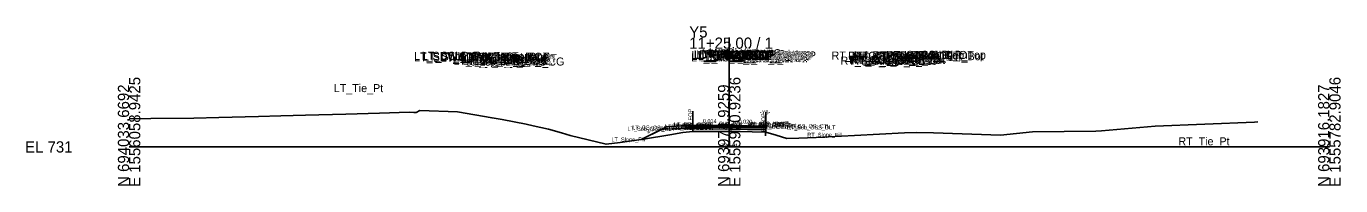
# Model space of a CAD drawing. Extents: x -26 to 4229, y -10 to 9523.
# Drawn here: x -25.7 to 302.8, y 1990.3 to 2030.1 of the extents above; entities that cross this region are included whole.
import ezdxf

# ---------------------------------------------------------------- set-up
doc = ezdxf.new("R2010")
doc.units = 0
for name, color, linetype in [('Default', 7, 'Continuous'), ('Exist Cross Section Cell', 7, 'Continuous'), ('Exist XS Center Line Elevation Label', 7, 'Continuous'), ('Exist XS Ground Line', 7, 'Continuous'), ('Old_Level_63', 7, 'Continuous'), ('Prop CMT Pvmt Course 1', 7, 'Continuous'), ('Prop CMT Pvmt Course 2', 7, 'Continuous'), ('Prop CMT Pvmt Course 3', 7, 'Continuous'), ('Prop CMT Pvmt Surface', 7, 'Continuous'), ('Prop CMT Pvmt Surface Shoulder', 7, 'Continuous'), ('Prop CMT Shld Paved Course 1', 7, 'Continuous'), ('Prop CMT Shld Paved Course 2', 7, 'Continuous'), ('Prop CMT Shld Paved Course 3', 7, 'Continuous'), ('Prop CMT Slope Grass', 7, 'Continuous'), ('Prop CMT Subgrade Earthwork', 7, 'Continuous'), ('Prop XS Earthwork Shape', 7, 'Continuous'), ('Prop XS Label Text', 7, 'Continuous'), ('Prop XSC Text', 7, 'Continuous'), ('Scratch_Level_1', 7, 'Continuous')]:
    doc.layers.add(name, color=color, linetype=linetype)

msp = doc.modelspace()

# ---------------------------------------------------------------- linework, layer by layer
at = {"layer": 'Exist Cross Section Cell'}
for p, q in [((150, 2000), (150, 2027.33)), ((0, 2000), (150, 2000)), ((150, 2000), (300, 2000))]:
    msp.add_line(p, q, dxfattribs=at)
at = {"layer": 'Exist XS Ground Line'}
msp.add_lwpolyline([(0, 2007.03), (5.43, 2007.07), (16.15, 2007.19), (22.43, 2007.34), (32.35, 2007.62), (37.96, 2007.79), (44.11, 2007.93), (54.16, 2008.19), (62.55, 2008.45), (70.03, 2008.64), (71.21, 2008.63), (71.78, 2008.63), (72.64, 2009.11), (82.09, 2008.73), (90.75, 2007.23), (93.26, 2006.81), (99.28, 2005.66), (101.04, 2005.27), (104.81, 2004.46), (108.09, 2003.48), (110.25, 2002.89), (119.22, 2000.68), (122.77, 2001.09), (128.6, 2001.91), (135.17, 2003.03), (138.44, 2003.62), (140.89, 2003.89), (147.47, 2003.83), (150, 2003.81), (150.37, 2003.81), (152.44, 2003.81), (159.14, 2003.65), (161.72, 2002.94), (164.41, 2002.07), (167.4, 2002.18), (173.89, 2002.43), (174.83, 2002.5), (181.29, 2002.88), (193.78, 2003.51), (196.75, 2003.64), (201.06, 2003.55), (217.77, 2002.96), (225.79, 2003.79), (241.6, 2003.97), (243.01, 2004), (256.47, 2005.22), (281.27, 2006.21), (282.14, 2006.25)], dxfattribs=at)
at = {"layer": 'Old_Level_63'}
msp.add_line((159.06, 2008.02), (159.06, 2002.73), dxfattribs=at)
at = {"layer": 'Prop CMT Pvmt Course 1'}
for points in [[(150, 2005.34), (140.3, 2005.47)], [(140.3, 2005.47), (140.3, 2005.22)], [(140.3, 2005.22), (150, 2005.09)], [(150, 2005.09), (150, 2005.34)], [(150, 2005.34), (159.06, 2005.15)], [(150, 2005.09), (150, 2005.34)], [(159.06, 2004.9), (150, 2005.09)], [(159.06, 2005.15), (159.06, 2004.9)]]:
    msp.add_lwpolyline(points, dxfattribs=at)
at = {"layer": 'Prop CMT Pvmt Course 2'}
for points in [[(150, 2005.09), (140.3, 2005.22)], [(140.3, 2005.22), (140.3, 2004.97)], [(140.3, 2004.97), (150, 2004.84)], [(150, 2004.84), (150, 2005.09)], [(150, 2004.84), (150, 2005.09)], [(150, 2005.09), (159.06, 2004.9)], [(159.06, 2004.65), (150, 2004.84)], [(159.06, 2004.9), (159.06, 2004.65)]]:
    msp.add_lwpolyline(points, dxfattribs=at)
at = {"layer": 'Prop CMT Pvmt Course 3'}
for points in [[(150, 2004.84), (140.3, 2004.97)], [(140.3, 2004.97), (140.3, 2004.6)], [(140.3, 2004.6), (150, 2004.46)], [(150, 2004.46), (150, 2004.84)], [(150, 2004.84), (159.06, 2004.65)], [(150, 2004.46), (150, 2004.84)], [(159.06, 2004.28), (150, 2004.46)], [(159.06, 2004.65), (159.06, 2004.28)]]:
    msp.add_lwpolyline(points, dxfattribs=at)
at = {"layer": 'Prop CMT Pvmt Surface'}
for points in [[(150, 2005.34), (140.3, 2005.47)], [(150, 2005.34), (159.06, 2005.15)]]:
    msp.add_lwpolyline(points, dxfattribs=at)
at = {"layer": 'Prop CMT Pvmt Surface Shoulder'}
for points in [[(140.3, 2005.47), (140.3, 2005.47)], [(159.06, 2005.15), (159.06, 2005.15)]]:
    msp.add_lwpolyline(points, dxfattribs=at)
at = {"layer": 'Prop CMT Shld Paved Course 1'}
for points in [[(140.3, 2005.47), (140.05, 2005.22)], [(140.05, 2005.22), (140.3, 2005.22)], [(140.3, 2005.47), (140.3, 2005.47)], [(140.3, 2005.22), (140.3, 2005.47)], [(159.06, 2005.15), (159.06, 2005.15)], [(159.06, 2004.9), (159.06, 2005.15)]]:
    msp.add_lwpolyline(points, dxfattribs=at)
at = {"layer": 'Prop CMT Shld Paved Course 2'}
for points in [[(140.3, 2005.22), (140.05, 2005.22), (139.79, 2004.96)], [(139.79, 2004.96), (140.3, 2004.97)], [(140.3, 2004.97), (140.3, 2005.22)], [(159.06, 2004.65), (159.06, 2004.9)]]:
    msp.add_lwpolyline(points, dxfattribs=at)
at = {"layer": 'Prop CMT Shld Paved Course 3'}
for points in [[(140.3, 2004.97), (139.79, 2004.96), (139.29, 2004.95), (138.91, 2004.57)], [(138.91, 2004.57), (140.3, 2004.6)], [(140.3, 2004.6), (140.3, 2004.97)], [(159.06, 2004.28), (159.06, 2004.65)]]:
    msp.add_lwpolyline(points, dxfattribs=at)
at = {"layer": 'Prop CMT Slope Grass'}
msp.add_lwpolyline([(140.3, 2005.47), (134.3, 2004.99), (127.97, 2001.82)], dxfattribs=at)
at = {"layer": 'Prop CMT Subgrade Earthwork'}
msp.add_line((159.06, 2005.15), (159.06, 2003.65), dxfattribs=at)
for points in [[(138.91, 2004.57), (133.23, 2004.46)], [(140.3, 2004.6), (138.91, 2004.57)], [(150, 2004.46), (140.3, 2004.6)], [(150, 2004.46), (159.06, 2004.28)], [(159.06, 2004.28), (159.06, 2003.65)]]:
    msp.add_lwpolyline(points, dxfattribs=at)
at = {"layer": 'Prop XS Earthwork Shape'}
msp.add_lwpolyline([(159.06, 2004.28), (159.06, 2003.65), (152.44, 2003.81), (150.37, 2003.81), (150, 2003.81), (147.47, 2003.83), (140.89, 2003.89), (138.44, 2003.62), (135.17, 2003.03), (128.6, 2001.91), (127.97, 2001.82), (133.23, 2004.46), (138.91, 2004.57), (140.3, 2004.6), (150, 2004.46)], close=True, dxfattribs=at)
at = {"layer": 'Prop XS Label Text'}
for p, q in [((140.89, 2008.89), (140.89, 2003.89)), ((159.14, 2008.65), (159.14, 2003.65))]:
    msp.add_line(p, q, dxfattribs=at)

# ---------------------------------------------------------------- texts
at = {"layer": 'Default'}
for s, height, p in [('LT_SDWK_Out_Top', 2, (71.24, 2021.75)), ('LT_CSLP_Pnt', 2, (73.17, 2021.78)), ('LT_PV2_OEEOP', 2, (140.56, 2021.99)), ('LT_PV3_OEEOP', 2, (140.56, 2021.74)), ('LT_PV1_OEEOP', 2, (141.12, 2022.11)), ('LT_PV2_IEEOP', 2, (141.2, 2021.99)), ('LT_PV1_IEEOP', 2, (141.77, 2022.11)), ('LT_PV2_PGL1', 2, (142.13, 2021.99)), ('LT_PV3_PGL1', 2, (142.13, 2021.74)), ('LT_PV2_PGL', 2, (142.46, 2021.99)), ('LT_PV1_PGL', 2, (143.03, 2022.24)), ('MI_Face In', 2, (143.15, 2022.4)), ('MI_Bot In', 2, (144.13, 2022.24)), ('MI_Top In', 2, (144.86, 2022.65)), ('MI_Crown', 2, (149.07, 2022.73)), ('RT_PV2_OEEOP', 2, (150.01, 2021.75)), ('RT_PV1_OEEOP', 2, (150.58, 2021.87)), ('RT_PV2_IEEOP', 2, (150.66, 2021.75)), ('MI_Face Out', 2, (151.01, 2022.16)), ('MI_Top Out', 2, (151.22, 2022.41)), ('RT_PV1_IEEOP', 2, (151.22, 2021.87)), ('RT_PV2_PGL1', 2, (151.58, 2021.75)), ('RT_PV2_PGL', 2, (151.92, 2021.75)), ('MI_Bot Out', 2, (152.01, 2022)), ('RT_PV1_PGL', 2, (152.48, 2022)), ('RT_Sub_Trench_Out_DLT', 2, (175.59, 2021.82)), ('RT_CG_Top_Face', 2, (179.71, 2021.78)), ('RT_CG_Top_BOC', 2, (181.24, 2021.78)), ('RT_SDWK_In_Top', 2, (185.81, 2021.89)), ('RT_SDWK_Out_Top', 2, (189.19, 2021.99)), ('RT_Shld_O', 2, (195.54, 2021.98)), ('CSLP_Pnt', 2, (197.87, 2022.02)), ('LT_SDWK_Out_Bot', 2, (71.27, 2021.42)), ('LT_Sub_Trench_Out_DLT', 2, (73.49, 2021.58)), ('LT_SDWK_In_Top', 2, (77.86, 2021.65)), ('LT_SDWK_In_Bot', 2, (77.89, 2021.32)), ('LT_CG1_Shelf_Out', 2, (81.05, 2020.52)), ('LT_CG_Top_Face', 2, (82.76, 2021.54)), ('LT_CG_Top_BOC', 2, (83.28, 2021.54)), ('LT_CG_Bot_BOC', 2, (83.31, 2020.53)), ('LT_CG_Top_Gut', 2, (83.74, 2021.04)), ('LT_Sub_OEOP', 2, (84.36, 2020.26)), ('LT_Sub_OEOT_CG', 2, (84.87, 2020.33)), ('LT_CG_Bot_IE', 2, (87.41, 2020.58)), ('LT_Sub_OEOT', 2, (87.58, 2020.29)), ('LT_PV2_OEOT', 2, (87.67, 2020.91)), ('LT_PV3_OEOT', 2, (87.67, 2020.66)), ('LT_PV1_OEOT', 2, (88.24, 2021.16)), ('LT_Sub_OEEOP', 2, (140.46, 2021.36)), ('LT_PV4_PGL', 2, (142.46, 2021.36)), ('RT_Sub_OEEOP', 2, (149.92, 2021.12)), ('RT_PV3_OEEOP', 2, (150.01, 2021.5)), ('RT_PV3_PGL1', 2, (151.58, 2021.5)), ('RT_PV4_PGL', 2, (151.92, 2021.12)), ('RT_Sub_OEOT_CG', 2, (177.82, 2020.57)), ('RT_CG1_Shelf_Out', 2, (180, 2020.76)), ('RT_CG_Bot_IE', 2, (180.37, 2020.82)), ('RT_Sub_OEOT', 2, (180.53, 2020.53)), ('RT_PV2_OEOT', 2, (180.63, 2021.15)), ('RT_PV3_OEOT', 2, (180.63, 2020.9)), ('RT_CG_Top_Gut', 2, (180.69, 2021.28)), ('RT_PV1_OEOT', 2, (181.19, 2021.4)), ('RT_CG_Bot_BOC', 2, (181.27, 2020.77)), ('RT_Sub_OEOP', 2, (183.82, 2020.5)), ('RT_SDWK_In_Bot', 2, (185.84, 2021.56)), ('RT_SDWK_Out_Bot', 2, (189.22, 2021.66)), ('LT_Tie_Pt', 2, (51.17, 2013.69)), ('RT_Tie_Pt', 2, (262.27, 2000.4)), ('-', 0.0001, (0, 2000)), ('-', 0.0001, (0, 2000)), ('-', 0.0001, (0, 2000)), ('-', 0.0001, (0, 2000)), ('-', 0.0001, (0, 2000)), ('-', 0.0001, (0, 2000)), ('-', 0.0001, (0, 2000)), ('-', 0.0001, (0, 2000)), ('-', 0.0001, (0, 2000)), ('-', 0.0001, (0, 2000))]:
    msp.add_text(s, height=height, dxfattribs=at).set_placement(p)
at = {"layer": 'Exist Cross Section Cell'}
for s, p in [('Y5', (140, 2027.33)), ('11+25.00 / 1', (140, 2024.53)), ('EL 731', (-26, 1998.6))]:
    msp.add_text(s, height=2.8, dxfattribs=at).set_placement(p)
for s, p in [('E 1556058.9425', (2.8, 1990)), ('E 1555920.9236', (152.8, 1990)), ('E 1555782.9046', (302.8, 1990)), ('N 694033.6692', (0, 1990)), ('N 693974.9259', (150, 1990)), ('N 693916.1827', (300, 1990))]:
    msp.add_text(s, height=2.8, rotation=90, dxfattribs=at).set_placement(p)
at = {"layer": 'Exist XS Center Line Elevation Label'}
msp.add_text('734.81', height=1, dxfattribs=at).set_placement((147.99, 1999.81))
at = {"layer": 'Prop XS Label Text'}
for p in [(140.79, 2004.91), (159.04, 2003.75)]:
    msp.add_text('E. EOP', height=1, rotation=90, dxfattribs=at).set_placement(p)
at = {"layer": 'Prop XSC Text'}
msp.add_text('-Y8-', height=1, dxfattribs=at).set_placement((157.67, 2008.16))
for s, rotation, p in [('2:1', 26.5651, (129.62, 2003.3)), ('0.014', 359.1979, (143.4, 2005.99)), ('0.020', 358.8542, (152.31, 2005.85))]:
    msp.add_text(s, height=1, rotation=rotation, dxfattribs=at).set_placement(p)
at = {"layer": 'Scratch_Level_1'}
for s, p in [('LT_Sub_OSS_DLT', (124.57, 2004.07)), ('LT_GS_OS_CTL', (125.76, 2004.35)), ('LT_Sub_Trench_Out', (133.02, 2004.25)), ('LT_PS3_Shelf_Out', (133.95, 2004.63)), ('LT_PS3_OEOP', (135.58, 2004.64)), ('LT_PS2_OEOP', (135.83, 2004.9)), ('LT_PV2_OEOT', (136.05, 2004.9)), ('LT_PV3_OEOT', (136.05, 2004.65)), ('LT_Sub_OEOT', (136.07, 2004.28)), ('LT_PV1_OEOT', (136.17, 2005.15)), ('LT_PS1_OEOP', (136.21, 2005.15)), ('Sub_PGL', (147.37, 2004.47)), ('PV2_PGL', (147.35, 2005.09)), ('PV3_PGL', (147.35, 2004.84)), ('PV1_PGL', (147.47, 2005.34)), ('RT_Sub_Trench_Out', (154.5, 2004.58)), ('RT_PS3_Shelf_Out', (154.67, 2004.96)), ('RT_PV2_OEOT', (154.74, 2005.23)), ('RT_PV3_OEOT', (154.74, 2004.98)), ('RT_Sub_OEOT', (154.77, 2004.6)), ('RT_PV1_OEOT', (154.86, 2005.48)), ('RT_PS1_OEOP', (154.91, 2005.48)), ('RT_PS2_OEOP', (155.04, 2005.22)), ('RT_PS3_OEOP', (155.3, 2004.97)), ('RT_Sub_OSS_DLT', (164.42, 2004.39)), ('RT_GS_OS_CTL', (164.46, 2004.68)), ('LT_Slope_Fill', (120.57, 2001.37)), ('RT_Slope_Fill', (169.53, 2002.53))]:
    msp.add_text(s, height=1, rotation=359.8763, dxfattribs=at).set_placement(p)

doc.saveas('drawing.dxf')
